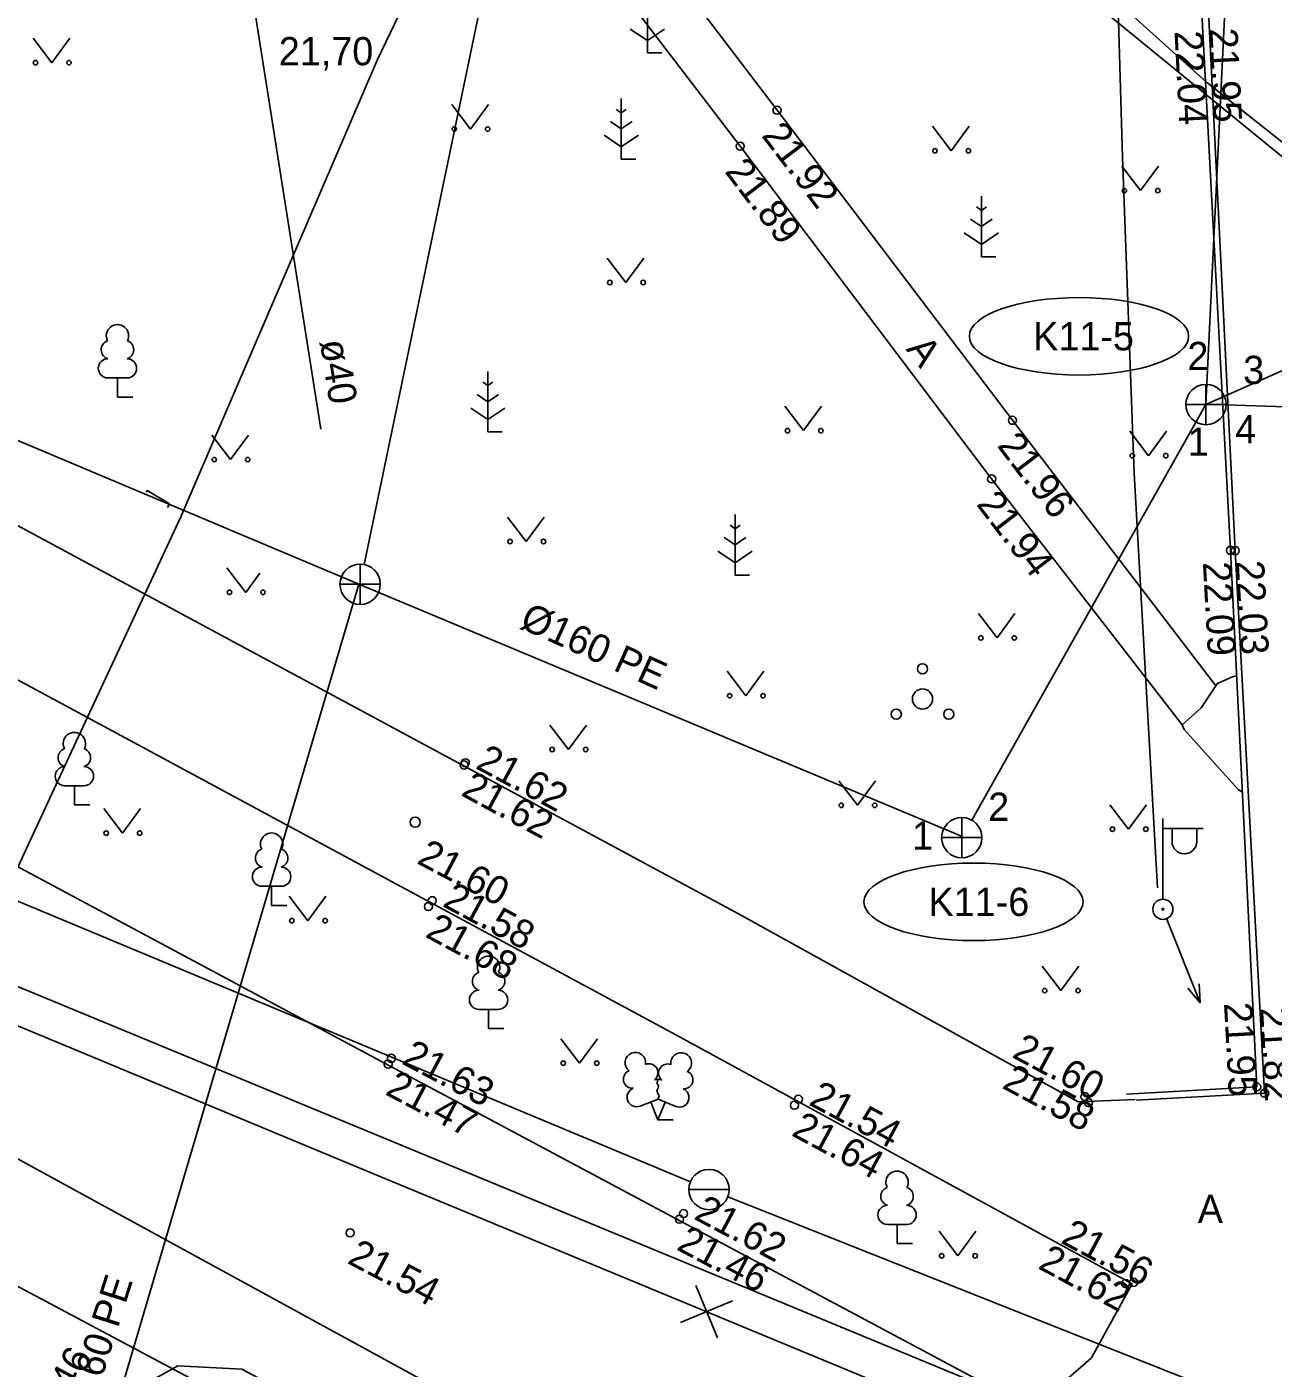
# Model space of a CAD drawing. Extents: x 714038 to 714279, y 6589845 to 6590041.
# Drawn here: x 714085.35 to 714116.25, y 6589987.55 to 6590020.81 of the extents above; entities that cross this region are included whole.
import ezdxf

# ---------------------------------------------------------------- set-up
doc = ezdxf.new("R2010")
doc.units = 0
for name, color, linetype in [('AED', 7, 'Continuous'), ('HALJASTUS', 7, 'Continuous'), ('HOONE', 7, 'Continuous'), ('KAEVU_NR', 7, 'Continuous'), ('KKAEV', 7, 'Continuous'), ('KORGUS', 7, 'Continuous'), ('KTRASS', 7, 'Continuous'), ('MPKAABEL', 7, 'Continuous'), ('MPOHULIIN', 7, 'Continuous'), ('POST', 7, 'Continuous'), ('PUU', 7, 'Continuous'), ('SITRASS', 7, 'Continuous'), ('SKTRASS', 7, 'Continuous'), ('TEE', 7, 'Continuous'), ('TORU NR', 7, 'Continuous'), ('VKAEV', 7, 'Continuous'), ('VTRASS', 7, 'Continuous')]:
    doc.layers.add(name, color=color, linetype=linetype)

msp = doc.modelspace()

# ---------------------------------------------------------------- linework, layer by layer
at = {"layer": 'AED'}
msp.add_lwpolyline([(714088.316, 6590009.269), (714088.34, 6590009.31), (714088.89, 6590008.98), (714088.841, 6590008.894)], dxfattribs=at)
at = {"layer": 'HALJASTUS'}
for p, q in [((714085.507, 6590020.527), (714085.97, 6590019.92)), ((714085.97, 6590019.92), (714086.416, 6590020.527)), ((714095.886, 6590018.881), (714096.35, 6590018.274)), ((714096.35, 6590018.274), (714096.795, 6590018.881)), ((714107.802, 6590018.343), (714108.265, 6590017.736)), ((714108.265, 6590017.736), (714108.711, 6590018.343)), ((714112.497, 6590017.355), (714112.961, 6590016.748)), ((714112.961, 6590016.748), (714113.406, 6590017.355)), ((714099.741, 6590015.077), (714100.205, 6590014.47)), ((714100.205, 6590014.47), (714100.65, 6590015.077)), ((714104.145, 6590011.404), (714104.609, 6590010.797)), ((714104.609, 6590010.797), (714105.054, 6590011.404)), ((714089.937, 6590010.687), (714090.4, 6590010.08)), ((714090.4, 6590010.08), (714090.846, 6590010.687)), ((714112.695, 6590010.784), (714113.158, 6590010.177)), ((714113.158, 6590010.177), (714113.604, 6590010.784)), ((714097.27, 6590008.654), (714097.733, 6590008.048)), ((714097.733, 6590008.048), (714098.179, 6590008.654)), ((714090.315, 6590007.395), (714090.778, 6590006.788)), ((714090.778, 6590006.788), (714091.128, 6590007.265)), ((714108.94, 6590006.266), (714109.403, 6590005.659)), ((714109.403, 6590005.659), (714109.848, 6590006.266)), ((714102.712, 6590004.833), (714103.176, 6590004.226)), ((714103.176, 6590004.226), (714103.621, 6590004.833)), ((714098.314, 6590003.499), (714098.777, 6590002.892)), ((714098.777, 6590002.892), (714099.223, 6590003.499)), ((714105.48, 6590002.116), (714105.943, 6590001.509)), ((714105.943, 6590001.509), (714106.389, 6590002.116)), ((714112.201, 6590001.523), (714112.665, 6590000.916)), ((714112.665, 6590000.916), (714113.11, 6590001.523)), ((714087.259, 6590001.427), (714087.722, 6590000.82)), ((714087.722, 6590000.82), (714088.168, 6590001.427)), ((714091.859, 6589999.255), (714092.322, 6589998.649)), ((714092.322, 6589998.649), (714092.768, 6589999.255)), ((714110.521, 6589997.521), (714110.984, 6589996.915)), ((714110.984, 6589996.915), (714111.43, 6589997.521)), ((714098.588, 6589995.722), (714099.052, 6589995.115)), ((714099.052, 6589995.115), (714099.497, 6589995.722)), ((714107.969, 6589990.948), (714108.432, 6589990.341)), ((714108.432, 6589990.341), (714108.878, 6589990.948))]:
    msp.add_line(p, q, dxfattribs=at)
for centre in [(714085.569, 6590019.92), (714086.398, 6590019.92), (714095.949, 6590018.274), (714096.777, 6590018.274), (714107.864, 6590017.736), (714108.693, 6590017.736), (714112.56, 6590016.748), (714113.388, 6590016.748), (714099.804, 6590014.47), (714100.632, 6590014.47), (714104.208, 6590010.797), (714105.037, 6590010.797), (714112.757, 6590010.177), (714113.586, 6590010.177), (714089.999, 6590010.08), (714090.828, 6590010.08), (714097.332, 6590008.048), (714098.161, 6590008.048), (714090.377, 6590006.788), (714091.206, 6590006.788), (714109.002, 6590005.659), (714109.831, 6590005.659), (714102.775, 6590004.226), (714103.603, 6590004.226), (714098.376, 6590002.892), (714099.205, 6590002.892), (714105.542, 6590001.509), (714106.371, 6590001.509), (714087.321, 6590000.82), (714088.15, 6590000.82), (714112.264, 6590000.916), (714113.093, 6590000.916), (714091.921, 6589998.649), (714092.75, 6589998.649), (714110.583, 6589996.915), (714111.412, 6589996.915), (714098.651, 6589995.115), (714099.48, 6589995.115), (714108.031, 6589990.341), (714108.86, 6589990.341)]:
    msp.add_circle(centre, 0.055, dxfattribs=at)
at = {"layer": 'HOONE'}
msp.add_lwpolyline([(714037.81, 6590017.576), (714059.08, 6590006.51), (714072.38, 6589999.69), (714082.14, 6589994.37), (714104.85, 6589981.96), (714150.21, 6589957.43), (714183.55, 6589939.45), (714202.68, 6589928.99), (714214.04, 6589922.75), (714222.92, 6589918.06), (714237.47, 6589910.29), (714252.27, 6589902.23), (714256.602, 6589899.815), (714258.577, 6589898.715), (714261.69, 6589896.98)], dxfattribs=at)
at = {"layer": 'KAEVU_NR'}
for centre in [(714111.435, 6590013.137), (714108.822, 6589999.116)]:
    msp.add_ellipse(centre, major_axis=(2.717, 0), ratio=0.353371, dxfattribs=at)
at = {"layer": 'KKAEV'}
for p, q in [((714114.583, 6590010.944), (714114.583, 6590011.944)), ((714114.083, 6590011.444), (714115.083, 6590011.444)), ((714093.616, 6590006.489), (714093.616, 6590007.489)), ((714093.116, 6590006.989), (714094.116, 6590006.989)), ((714108.53, 6590000.208), (714108.53, 6590001.208)), ((714108.03, 6590000.708), (714109.03, 6590000.708))]:
    msp.add_line(p, q, dxfattribs=at)
for centre in [(714114.583, 6590011.444), (714093.616, 6590006.989), (714108.53, 6590000.708)]:
    msp.add_circle(centre, 0.5, dxfattribs=at)
at = {"layer": 'KORGUS'}
for centre, radius in [((714103.95, 6590018.741), 0.1), ((714103.037, 6590017.849), 0.1), ((714109.785, 6590011.054), 0.1), ((714109.27, 6590009.601), 0.1), ((714115.19, 6590007.83), 0.1), ((714115.306, 6590007.823), 0.1), ((714096.192, 6590002.508), 0.1), ((714096.222, 6590002.563), 0.1), ((714094.98, 6590001.09), 0.125), ((714095.402, 6589999.144), 0.1), ((714095.308, 6589998.999), 0.1), ((714094.31, 6589995.093), 0.1), ((714094.39, 6589995.236), 0.1), ((714115.842, 6589994.528), 0.1), ((714104.481, 6589994.221), 0.1), ((714111.582, 6589994.285), 0.1), ((714111.668, 6589994.139), 0.1), ((714116.037, 6589994.37), 0.1), ((714104.383, 6589994.075), 0.1), ((714101.532, 6589991.246), 0.1), ((714101.632, 6589991.387), 0.1), ((714093.367, 6589990.91), 0.1), ((714112.589, 6589989.651), 0.1), ((714112.791, 6589989.683), 0.1)]:
    msp.add_circle(centre, radius, dxfattribs=at)
at = {"layer": 'KTRASS'}
for points in [[(714115.68, 6590034.214), (714114.583, 6590011.444)], [(714108.526, 6590000.746), (714093.581, 6590006.995), (714058.132, 6590021.931)], [(714114.583, 6590011.444), (714122.942, 6590015.15)], [(714114.583, 6590011.444), (714108.776, 6590001.144)], [(714114.552, 6590011.45), (714123.119, 6590011.176)], [(714082.125, 6589929.177), (714081.284, 6589949.55), (714080.742, 6589963.482), (714093.581, 6590006.995)]]:
    msp.add_lwpolyline(points, dxfattribs=at)
at = {"layer": 'MPKAABEL'}
for p, q in [((714101.933, 6589989.602), (714102.471, 6589988.309)), ((714101.555, 6589988.686), (714102.848, 6589989.224))]:
    msp.add_line(p, q, dxfattribs=at)
for points in [[(714113.38, 6589999.46), (714112.8, 6590009.74), (714112.51, 6590017.58), (714112.36, 6590022.95), (714112.51, 6590023.065)], [(714037.81, 6590016.164), (714045.98, 6590012.32), (714093.89, 6589992.4), (714122, 6589980.75)], [(714097.447, 6589982.821), (714094.758, 6589984.46), (714071.268, 6589996.96), (714071.088, 6589997.05)]]:
    msp.add_lwpolyline(points, dxfattribs=at)
at = {"layer": 'MPOHULIIN'}
for p, q in [((714113.607, 6589998.699), (714114.441, 6589996.609)), ((714114.441, 6589996.609), (714114.136, 6589996.974)), ((714114.441, 6589996.609), (714114.413, 6589997.084))]:
    msp.add_line(p, q, dxfattribs=at)
at = {"layer": 'POST'}
for p, q in [((714113.515, 6589999.181), (714113.515, 6590001.181)), ((714113.515, 6590000.931), (714114.515, 6590000.931)), ((714113.741, 6590000.61), (714113.741, 6590000.931)), ((714114.354, 6590000.61), (714114.354, 6590000.931))]:
    msp.add_line(p, q, dxfattribs=at)
for radius in [0.25, 0.0234]:
    msp.add_circle((714113.515, 6589998.931), radius, dxfattribs=at)
msp.add_arc((714114.048, 6590000.61), 0.306, 180, 0, dxfattribs=at)
at = {"layer": 'PUU'}
for p, q in [((714100.735, 6590021.663), (714100.735, 6590020.163)), ((714100.311, 6590020.752), (714100.735, 6590020.47)), ((714100.735, 6590020.47), (714101.159, 6590020.752)), ((714101.095, 6590020.163), (714100.735, 6590020.163)), ((714100.088, 6590019.03), (714100.088, 6590017.53)), ((714100.088, 6590018.28), (714099.821, 6590018.458)), ((714100.088, 6590018.68), (714099.964, 6590018.763)), ((714100.212, 6590018.763), (714100.088, 6590018.68)), ((714100.355, 6590018.458), (714100.088, 6590018.28)), ((714099.664, 6590018.119), (714100.088, 6590017.837)), ((714100.088, 6590017.837), (714100.512, 6590018.119)), ((714100.448, 6590017.53), (714100.088, 6590017.53)), ((714109.016, 6590016.609), (714109.016, 6590015.109)), ((714109.016, 6590016.259), (714108.892, 6590016.342)), ((714109.14, 6590016.342), (714109.016, 6590016.259)), ((714109.016, 6590015.859), (714108.749, 6590016.037)), ((714109.283, 6590016.037), (714109.016, 6590015.859)), ((714108.592, 6590015.698), (714109.016, 6590015.416)), ((714109.016, 6590015.416), (714109.44, 6590015.698)), ((714109.376, 6590015.109), (714109.016, 6590015.109)), ((714096.78, 6590012.264), (714096.78, 6590010.764)), ((714087.84, 6590012.105), (714087.36, 6590012.105)), ((714087.6, 6590011.63), (714087.6, 6590012.105)), ((714096.78, 6590011.914), (714096.656, 6590011.997)), ((714096.904, 6590011.997), (714096.78, 6590011.914)), ((714087.98, 6590011.63), (714087.6, 6590011.63)), ((714096.78, 6590011.514), (714096.513, 6590011.692)), ((714097.047, 6590011.692), (714096.78, 6590011.514)), ((714096.356, 6590011.353), (714096.78, 6590011.071)), ((714096.78, 6590011.071), (714097.204, 6590011.353)), ((714097.14, 6590010.764), (714096.78, 6590010.764)), ((714102.909, 6590008.717), (714102.909, 6590007.217)), ((714102.909, 6590008.367), (714102.785, 6590008.45)), ((714103.033, 6590008.45), (714102.909, 6590008.367)), ((714102.909, 6590007.967), (714102.642, 6590008.145)), ((714103.176, 6590008.145), (714102.909, 6590007.967)), ((714102.485, 6590007.806), (714102.909, 6590007.524)), ((714102.909, 6590007.524), (714103.333, 6590007.806)), ((714103.269, 6590007.217), (714102.909, 6590007.217)), ((714086.771, 6590001.994), (714086.291, 6590001.994)), ((714086.531, 6590001.519), (714086.531, 6590001.994)), ((714086.911, 6590001.519), (714086.531, 6590001.519)), ((714091.661, 6589999.502), (714091.181, 6589999.502)), ((714091.421, 6589999.027), (714091.421, 6589999.502)), ((714091.801, 6589999.027), (714091.421, 6589999.027)), ((714097.04, 6589996.448), (714096.56, 6589996.448)), ((714096.8, 6589995.973), (714096.8, 6589996.448)), ((714097.18, 6589995.973), (714096.8, 6589995.973)), ((714100.555, 6589994.048), (714101, 6589994.223)), ((714101, 6589994.223), (714101.44, 6589994.043)), ((714100.995, 6589993.713), (714100.82, 6589994.153)), ((714100.995, 6589993.713), (714101.175, 6589994.153)), ((714101.375, 6589993.713), (714100.995, 6589993.713)), ((714107.165, 6589991.118), (714106.685, 6589991.118)), ((714106.925, 6589990.643), (714106.925, 6589991.118)), ((714107.305, 6589990.643), (714106.925, 6589990.643))]:
    msp.add_line(p, q, dxfattribs=at)
msp.add_lwpolyline([(714101, 6589994.718), (714100.98, 6589994.643), (714100.98, 6589994.623), (714100.99, 6589994.593), (714101.01, 6589994.558), (714101.015, 6589994.538), (714101, 6589994.503), (714100.975, 6589994.453), (714100.97, 6589994.428), (714100.975, 6589994.413), (714100.985, 6589994.383), (714101.02, 6589994.323), (714101.025, 6589994.303), (714101.02, 6589994.283), (714101.005, 6589994.248), (714101, 6589994.223)], dxfattribs=at)
for centre, radius in [((714107.556, 6590004.894), 0.125), ((714107.556, 6590004.144), 0.25), ((714106.906, 6590003.769), 0.125), ((714108.206, 6590003.769), 0.125)]:
    msp.add_circle(centre, radius, dxfattribs=at)
for centre, radius, start, end in [((714087.6, 6590013.15), 0.277, 332.5799, 207.4201), ((714087.43, 6590012.803), 0.233, 109.0217, 253.1415), ((714087.77, 6590012.803), 0.233, 286.8508, 70.9859), ((714087.363, 6590012.342), 0.238, 90.0016, 269.3953), ((714087.837, 6590012.342), 0.238, 270.6047, 89.9984), ((714086.531, 6590003.039), 0.277, 332.5799, 207.4201), ((714086.361, 6590002.692), 0.233, 109.0217, 253.1415), ((714086.701, 6590002.692), 0.233, 286.8508, 70.9859), ((714086.294, 6590002.231), 0.238, 90.0016, 269.3953), ((714086.769, 6590002.231), 0.238, 270.6047, 89.9984), ((714091.421, 6590000.547), 0.277, 332.5799, 207.4201), ((714091.251, 6590000.199), 0.233, 109.0217, 253.1415), ((714091.591, 6590000.199), 0.233, 286.8508, 70.9859), ((714091.184, 6589999.739), 0.238, 90.0016, 269.3953), ((714091.659, 6589999.739), 0.238, 270.6047, 89.9984), ((714096.8, 6589997.493), 0.277, 332.5799, 207.4201), ((714096.63, 6589997.146), 0.233, 109.0217, 253.1415), ((714096.97, 6589997.146), 0.233, 286.8508, 70.9859), ((714096.563, 6589996.686), 0.238, 90.0016, 269.3953), ((714097.037, 6589996.686), 0.238, 270.6047, 89.9984), ((714100.438, 6589995.127), 0.256, 111.5027, 232.5173), ((714100.438, 6589995.127), 0.256, 350.4856, 111.5002), ((714101.574, 6589995.119), 0.256, 67.6168, 188.6314), ((714101.574, 6589995.119), 0.256, 306.5997, 67.6143), ((714100.364, 6589994.716), 0.224, 111.4304, 274.4987), ((714100.773, 6589994.877), 0.224, 308.5041, 111.5725), ((714101.236, 6589994.872), 0.225, 67.7016, 230.5126), ((714101.641, 6589994.706), 0.224, 264.6183, 67.6866), ((714100.999, 6589994.481), 0.237, 66.7655, 111.5015), ((714100.469, 6589994.272), 0.237, 111.5014, 291.5004), ((714101.53, 6589994.264), 0.237, 247.6166, 67.6155), ((714106.925, 6589992.163), 0.277, 332.5799, 207.4201), ((714106.755, 6589991.815), 0.233, 109.0217, 253.1415), ((714107.095, 6589991.815), 0.233, 286.8508, 70.9859), ((714106.688, 6589991.355), 0.238, 90.0016, 269.3953), ((714107.163, 6589991.355), 0.238, 270.6047, 89.9984)]:
    msp.add_arc(centre, radius, start, end, dxfattribs=at)
at = {"layer": 'SITRASS'}
for points in [[(714078.609, 6589985.937), (714086.299, 6590002.484), (714089.168, 6590008.661), (714094.05, 6590020), (714095.092, 6590022.185), (714097.899, 6590028.624), (714100.251, 6590033.606)], [(714119.667, 6590015.291), (714118.134, 6590016.633), (714114.596, 6590019.438), (714107.457, 6590025.877), (714104.409, 6590029.065), (714100.251, 6590033.606)], [(714037.81, 6590017.083), (714041.45, 6590015.4), (714049.64, 6590011.61), (714053.69, 6590009.84), (714078.46, 6589999.77), (714120.53, 6589982.37), (714120.99, 6589982.37), (714121.09, 6589982.42), (714121.19, 6589982.57), (714121.29, 6589982.87), (714121.49, 6589988.215), (714121.85, 6589997.82), (714121.9, 6589998.22), (714123.574, 6590001.009)]]:
    msp.add_lwpolyline(points, dxfattribs=at)
at = {"layer": 'SKTRASS'}
for points in [[(714093.717, 6590007.479), (714100.679, 6590040.965)], [(714092.643, 6590010.832), (714090.47, 6590024.61)]]:
    msp.add_lwpolyline(points, dxfattribs=at)
at = {"layer": 'TEE'}
for points in [[(714112.613, 6589994.344), (714115.842, 6589994.528), (714115.19, 6590007.83), (714114.489, 6590020.993), (714113.715, 6590036.469), (714113.516, 6590038.053), (714113.32, 6590038.801), (714112.982, 6590039.544), (714112.557, 6590040.196), (714112.043, 6590040.807), (714111.861, 6590040.965)], [(714112.052, 6590040.965), (714112.122, 6590040.905), (714112.679, 6590040.278), (714113.106, 6590039.617), (714113.451, 6590038.877), (714113.663, 6590038.097), (714113.843, 6590036.482), (714114.652, 6590021.023), (714115.306, 6590007.823), (714116.037, 6589994.37), (714112.851, 6589994.202)], [(714056.466, 6590027.31), (714056.476, 6590024.886), (714056.788, 6590023.888), (714058.417, 6590022.828), (714080.514, 6590010.928), (714103.015, 6589998.807), (714111.415, 6589994.157), (714112.824, 6589994.218)], [(714098.608, 6590023.642), (714103.037, 6590017.849), (714109.27, 6590009.601), (714113.995, 6590003.502), (714114.466, 6590003.929), (714114.829, 6590004.468), (714109.785, 6590011.054), (714103.95, 6590018.741), (714099.329, 6590024.823)], [(714115.343, 6590004.716), (714115.257, 6590004.7), (714114.866, 6590004.531), (714114.829, 6590004.468)], [(714113.995, 6590003.502), (714114.041, 6590003.391), (714115.38, 6590001.903), (714115.484, 6590001.834)], [(714123.973, 6589969.784), (714113.651, 6589975.327), (714090.687, 6589987.533), (714089.1, 6589987.616), (714087.707, 6589986.834), (714086.427, 6589984.934), (714108.053, 6589973.169), (714127.373, 6589962.843)]]:
    msp.add_lwpolyline(points, dxfattribs=at)
msp.add_lwpolyline([(714111.749, 6589987.81), (714112.752, 6589989.647), (714101.456, 6589995.811), (714078.958, 6590007.942), (714056.863, 6590019.705), (714055.67, 6590019.684), (714056.126, 6590016.909), (714056.904, 6590015.524), (714058.111, 6590014.408), (714066.132, 6590010.156), (714094.483, 6589994.979), (714109.175, 6589987.135), (714110.128, 6589986.933), (714111.028, 6589987.18)], close=True, dxfattribs=at)
at = {"layer": 'VKAEV'}
msp.add_line((714101.764, 6589991.983), (714102.764, 6589991.983), dxfattribs=at)
msp.add_circle((714102.264, 6589991.983), 0.5, dxfattribs=at)
at = {"layer": 'VTRASS'}
for points in [[(714110.18, 6590040.965), (714110.16, 6590022.75), (714121.63, 6590013.38), (714123.019, 6590013.414)], [(714037.81, 6590019.066), (714045.328, 6590015.922), (714081.738, 6590000.542), (714101.803, 6589992.176)], [(714102.729, 6589991.799), (714114.744, 6589987.033), (714134.634, 6589979.269)]]:
    msp.add_lwpolyline(points, dxfattribs=at)

# ---------------------------------------------------------------- texts
at = {"layer": 'KAEVU_NR'}
for s, p in [('K11-5', (714110.299, 6590012.787)), ('K11-6', (714107.704, 6589998.766))]:
    msp.add_text(s, height=0.7, dxfattribs=at).set_placement(p)
at = {"layer": 'KORGUS'}
msp.add_text('21,70', height=0.7, dxfattribs=at).set_placement((714091.599, 6590019.855))
for s, rotation, p in [(' 22.04', 272.8364, (714113.79, 6590020.958)), (' 21.95', 272.8364, (714114.652, 6590021.023)), (' 21.92', 307.2012, (714103.392, 6590018.318)), (' 21.89', 307.2012, (714102.479, 6590017.426)), (' 21.96', 307.4473, (714109.229, 6590010.628)), (' 21.94', 307.4473, (714108.714, 6590009.175)), (' 22.09', 273.1102, (714114.491, 6590007.792)), (' 22.03', 273.1102, (714115.306, 6590007.823)), (' 21.62', 331.5886, (714096.222, 6590002.563)), (' 21.62', 331.5886, (714095.859, 6590001.892)), ('21,60', 332.1011, (714094.993, 6590000.083)), (' 21.58', 331.5162, (714095.402, 6589999.144)), (' 21.68', 331.5162, (714094.974, 6589998.384)), (' 21.95', 273.1102, (714115.014, 6589996.866)), (' 21.82', 273.1102, (714115.908, 6589996.746)), (' 21.63', 332.0101, (714094.39, 6589995.236)), (' 21.60', 331.6292, (714109.519, 6589995.399)), (' 21.47', 332.0101, (714093.981, 6589994.475)), (' 21.58', 331.6292, (714109.272, 6589994.637)), (' 21.54', 331.6701, (714104.481, 6589994.221)), (' 21.64', 331.6701, (714104.051, 6589993.459)), (' 21.62', 331.957, (714101.632, 6589991.387)), (' 21.56', 331.6701, (714110.727, 6589990.796)), (' 21.46', 331.957, (714101.203, 6589990.628)), (' 21.54', 332.171, (714093.04, 6589990.291)), (' 21.62', 331.6701, (714110.162, 6589990.164)), ('21,46', 62.0266, (714085.9, 6589985.769))]:
    msp.add_text(s, height=0.7, rotation=rotation, dxfattribs=at).set_placement(p)
at = {"layer": 'KTRASS'}
for rotation, p in [(335.6802, (714097.538, 6590005.921)), (72.4078, (714086.838, 6589986.099))]:
    msp.add_text('%%c160 PE', height=0.7, rotation=rotation, dxfattribs=at).set_placement(p)
at = {"layer": 'TEE'}
msp.add_text('A', height=0.7, rotation=307.2012, dxfattribs=at).set_placement((714107.132, 6590012.814))
msp.add_text('A', height=0.7, dxfattribs=at).set_placement((714114.379, 6589991.153))
at = {"layer": 'TORU NR'}
msp.add_text('ø40', height=0.7, rotation=278.7889, dxfattribs=at).set_placement((714092.616, 6590013.01))
for s, p in [('2', (714114.123, 6590012.298)), ('3', (714115.504, 6590011.953)), ('4', (714115.306, 6590010.482)), ('1', (714114.132, 6590010.175)), ('2', (714109.184, 6590001.124)), ('1', (714107.298, 6590000.41))]:
    msp.add_text(s, height=0.7, dxfattribs=at).set_placement(p)

doc.saveas('drawing.dxf')
